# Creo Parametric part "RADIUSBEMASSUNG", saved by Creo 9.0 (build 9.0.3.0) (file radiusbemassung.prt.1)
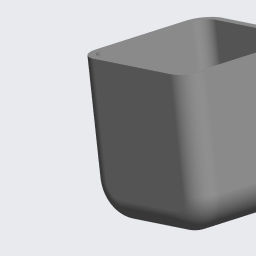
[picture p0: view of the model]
Materials in the file: S235JRG2

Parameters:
  BENENNUNG = "XXX"
  DATUM = "XX.XX.XX"
  ERSTELLER = "ARINDA"
  TEILETYP = "Fertigungsteil"
  PTC_MASTER_MATERIAL = "S235JRG2"
  SELECT_EN_NAME = "S235JRG2"
  SELECT_DIN_NAME = "RSt37-2"
  SELECT_DIN_NUMBER = "1.0038"
  SELECT_ASTM_NAME = "A 283 M Grade 2"
  MATERIAL_GROUP = "ME_ST_Baustahl"
  STANDARD_EN_DELIVERYSPEC = "DIN EN 10025"
  STANDARD_DIN_DELIVERYSPEC = "DIN 17100"

Other parameters: MASSE

Created from: ARINDA-STARTTEIL.PRT

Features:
  1. coordinate system "CS0"
  2. datum plane "DTM1", "T_RECHTS_Y-Z"
  3. datum plane "DTM2", "T_OBEN_X-Z"
  4. datum plane "DTM3", "T_VORNE_X-Y"
  5. datum axis "T_X-ACHSE"
  6. datum axis "A_1"
  7. datum axis "A_2"
  8. extrusion "Profil 1"
  9. round "Rundung 1"
  10. shell "Schale 1"

Other named items: T_BASIC, T_Y-ACHSE, T_Z-ACHSE

Layers: 00_STD-ACHSEN, 00_STD-EBENEN, 00_STD-KOORDSYS, VOLUMENGEOMETRIE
